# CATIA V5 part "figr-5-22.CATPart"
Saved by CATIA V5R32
Part number: Part1
Bounding box of the stored display mesh (mm): x -50 to 50, y 0 to 90.129, z 0 to 181.346
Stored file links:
  D:\PROJECTS\Project 2022\CATIA V5 6R 2022\Resources\Part Files\c05_catia_v5_6r2022_prt\figr-5-22.CATPart
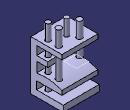
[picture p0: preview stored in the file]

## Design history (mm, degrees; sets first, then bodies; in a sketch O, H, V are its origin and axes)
Set1
  Plane1: type Offset, RefPlane face of Pad1, Offset 44, reversed
  Plane2: type Offset, RefPlane face of Pad1, Offset -46, reversed
Body1 (main body)
  Sketch1 on yz-plane, origin (0, 0, 0), H (0, 1, 0), V (0, 0, 1)
    line L1 (0, 0) -> (90.1292, 0)
    line L2 (90.1292, 0) -> (90.1292, 17.5473)
    line L3 (90.1292, 17.5473) -> (15.9521, 17.5473)
    line L4 (15.9521, 17.5473) -> (15.9521, 39.2532)
    line L5 (15.9521, 39.2532) -> (86.4281, 39.2532)
    line L6 (86.4281, 39.2532) -> (86.4281, 51.1017)
    arc A1 centre (39.4717, -66.63) radius 126.7503 from (86.4281, 51.1017) to (16.1896, 57.9637) ccw
    line L7 (16.1896, 57.9637) -> (16.1896, 86.2043)
    line L8 (16.1896, 86.2043) -> (46.6673, 86.2043)
    line L9 (46.6673, 86.2043) -> (46.6673, 100.2494)
    line L10 (46.6673, 100.2494) -> (16.1896, 100.2494)
    point P12 (16.1896, 100.2494)
    line L11 (16.1896, 100.2494) -> (16.1896, 124.3269)
    line L12 (16.1896, 124.3269) -> (86.4281, 124.3269)
    point P14 (86.4281, 124.3269)
    line L13 (86.4281, 124.3269) -> (86.4281, 137.3459)
    line L14 (86.4281, 137.3459) -> (0, 137.3459)
    point P16 (0, 137.3459)
    line L15 (0, 137.3459) -> (0, 0)
    horizontal: L1 H, L3 H, L5 H, L8 H, L10 H, L12 H, L14 H
    vertical: L2 V, L4 V, L6 V, L7 V, L9 V, L11 V, L13 V, L15 V
    coincidence: P12 L7, P14 L6, P16 V
  Pad1: profile Sketch1, direction (1, 0, 0), length 50, mirrored extent
  Sketch2 on Plane1, origin (0, 0, 181.3459), H (1, 0, 0), V (0, 1, 0)
    circle A1 centre (33.9095, 61.631) radius 7.5057
  Pad2: profile Sketch2, direction (0, 0, -1), up to face of Pad1
  Sketch3 on Plane1, origin (0, 0, 181.3459), H (1, 0, 0), V (0, -1, 0)
    circle A1 centre (-16.2674, -69.1948) radius 7.8522
  Pad3: profile Sketch3, direction (0, 0, -1), up to Plane2
  Sketch4 on Plane1, origin (0, 0, 181.3459), H (1, 0, 0), V (0, -1, 0)
    circle A1 centre (34.469, -32.4508) radius 7.1315
  Pad4: profile Sketch4, direction (0, 0, -1), up to the existing solid (limit type 3)
  Sketch5 on Plane1, origin (0, 0, 181.3459), H (1, 0, 0), V (0, -1, 0)
    circle A1 centre (-3.1833, -46.4863) radius 6.6131
  Pad5: profile Sketch5, direction (0, 0, -1), up to the existing solid (limit type 2)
